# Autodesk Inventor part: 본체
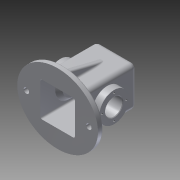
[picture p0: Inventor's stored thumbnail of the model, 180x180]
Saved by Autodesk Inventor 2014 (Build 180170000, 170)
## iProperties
Created: 2017-07
Part Number: 본체
Material: Aluminum 6061
Document SubType Name: Modeling
Designer: user
Density: 2.71 g/cm^3
Appearance: Aluminum - Flat
Author: user
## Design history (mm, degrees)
sketch "Sketch1" dims "d0" = 65, "d1" = 75
  geometry: 2 further points; 1 other entity
  constraints: 1 coincident, 2 other
extrude "Extrusion1" new body sketch "Sketch1" distance "d2" = 10; taper "d3" = 0 deg
sketch "Sketch2"
  geometry: L1 (-37, -37)-(37, -37); L2 (37, -37)-(37, 37); L3 (37, 37)-(-37, 37); L4 (-37, 37)-(-37, -37); L5 (-37, -37)-(37, 37); L6 (37, -37)-(-37, 37); 1 further point; 1 other entity
  constraints: 12 end point, 2 midpoint, 1 other
extrude "Extrusion2" join sketch "Sketch2" distance "d4" = 100; taper "d5" = 0 deg
sketch "Sketch3"
  geometry: L1 (-20, -20)-(20, -20); L2 (20, -20)-(20, 20); L3 (20, 20)-(-20, 20); L4 (-20, 20)-(-20, -20); L5 (-20, -20)-(20, 20); L6 (20, -20)-(-20, 20); 1 further point
  constraints: 12 end point, 2 midpoint
extrude "Extrusion3" join sketch "Sketch3" distance "d6" = 10; taper "d7" = -5 deg
sketch "Sketch4"
  geometry: L1 (-28, -10)-(102, -10) reference; C1 r 27.5 at (37, 45); 1 further point
  constraints: 1 centre point
  dimensions: "d8" = 55 distance from line of L1 C1.centre; "d9" = 55 diameter of C1
extrude "Extrusion4" join sketch "Sketch4" distance "d10" = 13; taper "d11" = 0 deg
sketch "Sketch5"
  geometry: L1 (32, 32)-(-32, 32); L2 (-32, 32)-(-32, -32); L3 (-32, -32)-(32, -32); L4 (32, -32)-(32, 32); L5 (32, 32)-(-32, -32); L6 (-32, 32)-(32, -32); 1 further point; 1 other entity
  constraints: 12 end point, 2 midpoint, 1 other
  dimensions: "d12" = 64 distance of L2.end L3.end; "d13" = 64 distance of L1.end L2.end
extrude "Extrusion5" cut sketch "Sketch5" distance "d14" = 105; taper "d15" = 0 deg
sketch "Sketch6"
  geometry: C1 r 14 at (0, 0); 1 further point
  constraints: 1 centre point, 1 coincident
  dimensions: "d16" = 28 diameter of C1
extrude "Extrusion6" cut sketch "Sketch6" distance "d17" = 4; taper "d18" = 0 deg
sketch "Sketch7"
  geometry: C1 r 14 at (0, 0) reference; C2 r 10.5 at (0, 0)
  constraints: 1 centre point, 1 coincident
  dimensions: "d19" = 21 diameter of C2
extrude "Extrusion7" cut sketch "Sketch7" stored distance "d20" = 4; taper "d21" = 0 deg
sketch "Sketch9"
  geometry: L1 (-33, 0)-(97, 0) reference; C1 r 27.5 at (32, 55); 1 further point
  constraints: 1 centre point
  dimensions: "d22" = 55 diameter of C1; "d23" = 55 distance from line of L1 C1.centre
extrude "Extrusion8" join sketch "Sketch9" distance "d24" = 7; taper "d25" = -45 deg
sketch "Sketch11"
  geometry: C1 r 27.5 at (0, 0) reference; C2 r 16 at (0, 0); 1 further point
  constraints: 1 centre point, 1 coincident
  dimensions: "d26" = 32 diameter of C2
extrude "Extrusion9" cut sketch "Sketch11" stored distance "d27" = 7; taper "d28" = 0 deg
sketch "Sketch12"
  geometry: L1 (0, -22.5)-(0, 22.5); L2 (22.5, 0)-(-22.5, 0); A1 r 22.5 centre (0, 0) between (0, 22.5) and (0, -22.5); 2 further points
  constraints: 4 end point, 4 point on circle, 1 centre point, 1 coincident, 1 midpoint
  dimensions: "d29" = 45 diameter of A1
hole "Hole2" sketch "Sketch12" at (0, 22.5), (22.5, 0), (0, -22.5), (-22.5, 0) diameter "d37" = 3.459; stored, may be unused: countersink angle "d41" = 90 deg, drill point angle "d43" = 118 deg; dims "d38" = 8, "d39" = 4, "d40" = 2, "d42" = 10
workplane "Work Plane1"
mirror "Mirror1"
sketch "Sketch13"
  geometry: L1 (74, 0)-(74, 100) reference; L2 (56.125, 110)-(17.875, 110) reference; L3 (16.577, 82.825)-(58.056, 82.825); L4 (58.056, 82.825)-(58.056, 76.821); L5 (58.056, 76.821)-(16.577, 76.821); L6 (16.577, 76.821)-(16.577, 82.825); 2 further points
  constraints: 2 other
  dimensions: "d44" = 30 distance from line of L2 point (37, 80); "d45" = 37 distance from line of point (37, 80) L1
emboss "Emboss1" sketch "Sketch13" dims "d46" = 0.5, "d47" = 0
sketch "Sketch14"
  geometry: L1 (10, -65)-(10, 65) reference; L2 (0, 65)-(0, -65) reference; L3 (10, 55)-(82.194, 37); L4 (82.194, 37)-(10, 37); 1 further point
  constraints: 4 end point, 2 point on line
  dimensions: "d49" = 10 distance of L3.start L1.end; "d50" = 14 deg angle of L4 L3
extrude "Extrusion10" join sketch "Sketch14" stored distance "d51" = 10; taper "d52" = 0 deg
fillet "Fillet1" dims "d53" = 8
workplane "Work Plane2"
mirror "Mirror2"
fillet "Fillet2" dims "d54" = 3
fillet "Fillet3" dims "d55" = 3
fillet "Fillet4" dims "d56" = 3
fillet "Fillet5" dims "d57" = 0.5
chamfer "Chamfer1" distance "d58" = 1; stored, may be unused: second distance "d59" = 2, angle "d60" = 45 deg
fillet "Fillet6" dims "d61" = 0.5
fillet "Fillet7" dims "d62" = 3
sketch "Sketch15"
  geometry: L1 (-58, 0)-(58, 0); C1 r 5 at (-58, 0); C2 r 5 at (58, 0); 1 further point; 1 other entity
  constraints: 2 centre point, 2 end point, 1 other
  dimensions: "d63" = 58 distance of point (0, 0) L1.end; "d64" = 58 distance of L1.start point (0, 0)
extrude "Extrusion11" cut sketch "Sketch15" distance "d65" = 10; taper "d66" = 0 deg
fillet "Fillet8" dims "d67" = 3
body "Solid1"
node "Projected Loop1"
